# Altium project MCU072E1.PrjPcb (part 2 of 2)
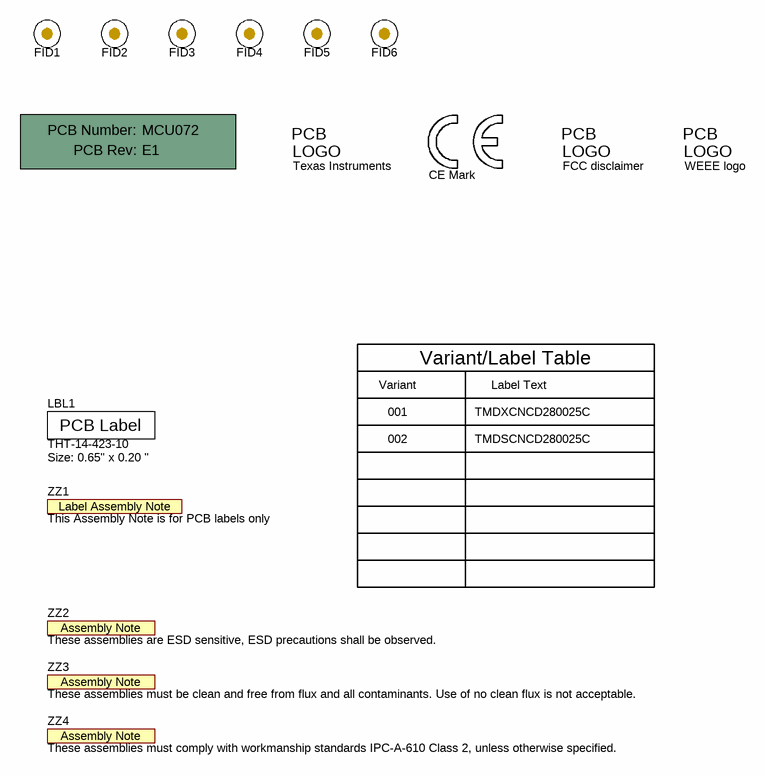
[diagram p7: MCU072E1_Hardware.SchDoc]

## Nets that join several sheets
3V3: MCU072E1_GPIO (J1.10 R1.1 R2.2), MCU072E1_Power (21 pins), MCU072E1_Emulator_Interface (10 pins)
EMU_3V3: MCU072E1_Emulator_Hardware (21 pins), MCU072E1_Emulator_Interface (6 pins)
EMU_GND: MCU072E1_Emulator_Hardware (41 pins), MCU072E1_Emulator_Interface (7 pins)
GND: MCU072E1_GPIO (14 pins), MCU072E1_Power (39 pins), MCU072E1_ADC (24 pins), MCU072E1_Emulator_Interface (13 pins)
HSEC_5V0: MCU072E1_GPIO (EC1.48 EC1.84 EC1.98 EC1.112), MCU072E1_Power (5 pins)
MCU_A_3V3: MCU072E1_Power (C11.2 C16.1 L2.2 U1.26), MCU072E1_ADC (6 pins)
EMU_SCI-RX: MCU072E1_Emulator_Hardware (U2:A.38), MCU072E1_Emulator_Interface (U5:A.3)
EMU_SCI-TX: MCU072E1_Emulator_Hardware (U2:A.39), MCU072E1_Emulator_Interface (U8:A.6)
EMU_TCK: MCU072E1_Emulator_Hardware (R3:A.1 U2:A.16), MCU072E1_Emulator_Interface (U6:A.2)
EMU_TDI: MCU072E1_Emulator_Hardware (U2:A.17), MCU072E1_Emulator_Interface (U5:A.2)
EMU_TDO: MCU072E1_Emulator_Hardware (U2:A.18), MCU072E1_Emulator_Interface (U8:A.7)
EMU_TMS: MCU072E1_Emulator_Hardware (R2:A.1 U2:A.19), MCU072E1_Emulator_Interface (U6:A.3)
HSEC_A0/C15: MCU072E1_GPIO (EC1.9), MCU072E1_ADC (R23.2 U5.1)
HSEC_A1: MCU072E1_GPIO (EC1.11), MCU072E1_ADC (R24.2 U5.3)
HSEC_A2/C9: MCU072E1_GPIO (EC1.15), MCU072E1_ADC (R25.2 U5.6)
HSEC_A3/C5/VDAC: MCU072E1_GPIO (EC1.17), MCU072E1_ADC (R26.2 U5.4)
HSEC_A4/C14: MCU072E1_GPIO (EC1.21), MCU072E1_ADC (R27.2 U7.3)
HSEC_A5/C2: MCU072E1_GPIO (EC1.23), MCU072E1_ADC (R28.2 U7.1)
HSEC_A6: MCU072E1_GPIO (EC1.25), MCU072E1_ADC (R29.2 U6.1)
HSEC_A7/C3: MCU072E1_GPIO (EC1.27), MCU072E1_ADC (R30.2 U8.4)
HSEC_A9/C8: MCU072E1_GPIO (EC1.26), MCU072E1_ADC (R32.2 U6.6)
HSEC_A10/C10: MCU072E1_GPIO (EC1.28), MCU072E1_ADC (R33.2 U8.1)
HSEC_A11/C0: MCU072E1_GPIO (EC1.12), MCU072E1_ADC (R34.2 U6.3)
HSEC_A12/C1: MCU072E1_GPIO (EC1.14), MCU072E1_ADC (R35.2 U8.6)
HSEC_A14/C4: MCU072E1_GPIO (EC1.18), MCU072E1_ADC (R36.2 U7.4)
HSEC_A15/C7: MCU072E1_GPIO (EC1.24), MCU072E1_ADC (R37.2 U7.6)
HSEC_C6: MCU072E1_GPIO (EC1.20), MCU072E1_ADC (R38.2 U6.4)
HSEC_GPIO18: MCU072E1_GPIO (EC1.71), MCU072E1_Power (S3.6)
HSEC_GPIO19: MCU072E1_GPIO (EC1.73), MCU072E1_Power (S3.3)
HSEC_pin30: MCU072E1_GPIO (EC1.30), MCU072E1_ADC (S5.4)
HSEC_pin34: MCU072E1_GPIO (EC1.34), MCU072E1_ADC (S5.6)
HSEC_VREFHI: MCU072E1_GPIO (EC1.45), MCU072E1_ADC (S5.1)
MCU_GPIO18: MCU072E1_GPIO (U1.50), MCU072E1_Power (S3.5)
MCU_GPIO19: MCU072E1_GPIO (U1.51), MCU072E1_Power (S3.2)
MCU_GPIO24: MCU072E1_GPIO (S1.2 U1.41), MCU072E1_Power (R17.2)
MCU_GPIO28: MCU072E1_GPIO (EC1.76 U1.4), MCU072E1_Emulator_Interface (U7:A.9)
MCU_GPIO29: MCU072E1_GPIO (EC1.78 U1.3), MCU072E1_Emulator_Interface (U7:A.13)
MCU_GPIO31: MCU072E1_GPIO (EC1.82 U1.2), MCU072E1_Power (R13.1 U2.1)
MCU_GPIO32: MCU072E1_GPIO (EC1.85 U1.49), MCU072E1_Power (R18.1)
MCU_GPIO34: MCU072E1_GPIO (EC1.86 U1.77), MCU072E1_Power (R14.1 U2.3)
MCU_GPIO35/TDI: MCU072E1_GPIO (EC1.8 R9.1), MCU072E1_Power (U1.48), MCU072E1_Emulator_Interface (U7:A.18)
MCU_GPIO37/TDO: MCU072E1_GPIO (EC1.6 R8.1), MCU072E1_Power (U1.46), MCU072E1_Emulator_Interface (U7:A.8)
MCU_TCK: MCU072E1_GPIO (EC1.5), MCU072E1_Power (U1.45), MCU072E1_Emulator_Interface (U7:A.16)
MCU_TMS: MCU072E1_GPIO (EC1.3), MCU072E1_Power (R22.1 U1.47), MCU072E1_Emulator_Interface (U7:A.14)
MCU_XRSn: MCU072E1_GPIO (EC1.120), MCU072E1_Power (5 pins)

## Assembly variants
001: not fitted C29 C30 C31 C32 C33 C34 C35 C36 C37 C38 C39 C40 C41 C42 C43 C44 FID1 FID2 FID3 FID4 FID5 FID6
002: not fitted C29 C30 C31 C32 C33 C34 C35 C36 C37 C38 C39 C40 C41 C42 C43 C44 FID1 FID2 FID3 FID4 FID5 FID6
